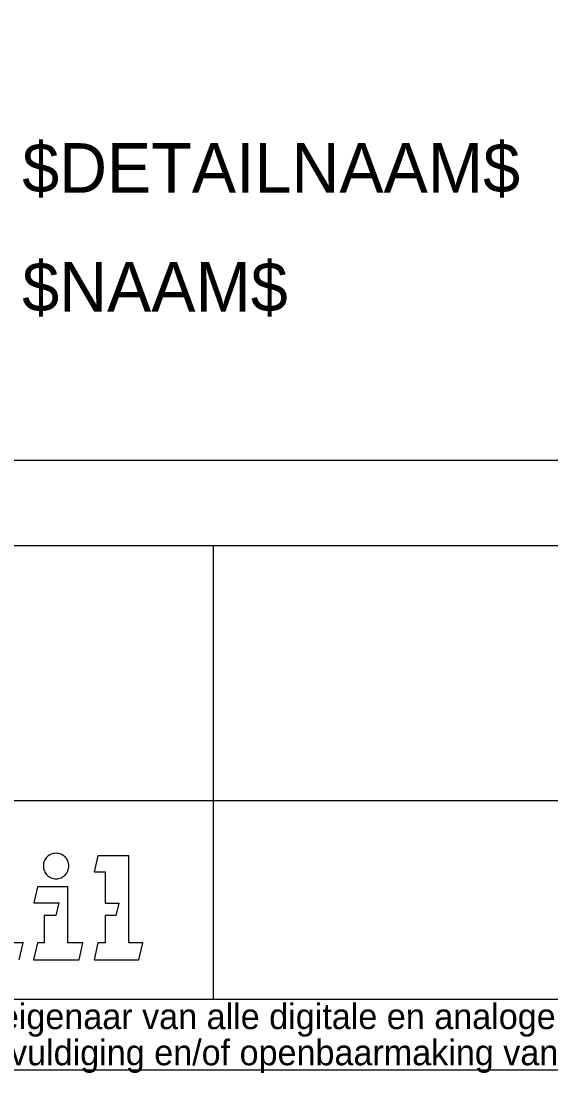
# Model space of a CAD drawing. Extents: x 0 to 1051, y 0 to 297.
# Drawn here: x 902.4 to 939.8, y -0.2 to 74 of the extents above; entities that cross this region are included whole.
import ezdxf

# ---------------------------------------------------------------- set-up
doc = ezdxf.new("R2010")
doc.units = 0
for name, color, linetype in [('KADER-LIJNEN-018', 7, 'Continuous'), ('KADER-LIJNEN-050', 7, 'Continuous'), ('TITEL-DETAIL', 7, 'Continuous'), ('TITEL-LIJNEN-050', 7, 'Continuous'), ('TITEL-PRORAIL', 7, 'Continuous'), ('TITEL-TEKSTEN-018', 7, 'Continuous')]:
    doc.layers.add(name, color=color, linetype=linetype)

msp = doc.modelspace()

# ---------------------------------------------------------------- linework, layer by layer
at = {"layer": 'KADER-LIJNEN-018'}
msp.add_line((0, 0), (1051, 0), dxfattribs=at)
at = {"layer": 'KADER-LIJNEN-050'}
msp.add_lwpolyline([(25, 5), (1046, 5), (1046, 292), (25, 292)], close=True, dxfattribs=at)
at = {"layer": 'TITEL-LIJNEN-050'}
for p, q in [((866, 37), (1046, 37)), ((916, 5), (916, 37)), ((866, 19), (1046, 19))]:
    msp.add_line(p, q, dxfattribs=at)
msp.add_lwpolyline([(866, 5), (1046, 5), (1046, 43), (866, 43)], close=True, dxfattribs=at)
at = {"layer": 'TITEL-PRORAIL'}
for p, q in [((904.147, 14.897), (904.098, 14.826)), ((904.195, 14.967), (904.147, 14.897)), ((904.255, 15.026), (904.195, 14.967)), ((904.314, 15.086), (904.255, 15.026)), ((904.384, 15.134), (904.314, 15.086)), ((904.455, 15.183), (904.384, 15.134)), ((904.536, 15.215), (904.455, 15.183)), ((904.617, 15.248), (904.536, 15.215)), ((904.703, 15.269), (904.617, 15.248)), ((904.795, 15.28), (904.703, 15.269)), ((904.886, 15.285), (904.795, 15.28)), ((904.978, 15.28), (904.886, 15.285)), ((905.065, 15.269), (904.978, 15.28)), ((905.156, 15.248), (905.065, 15.269)), ((905.237, 15.215), (905.156, 15.248)), ((905.318, 15.183), (905.237, 15.215)), ((905.389, 15.134), (905.318, 15.183)), ((905.464, 15.086), (905.389, 15.134)), ((905.524, 15.026), (905.464, 15.086)), ((905.583, 14.967), (905.524, 15.026)), ((905.637, 14.897), (905.583, 14.967)), ((905.68, 14.826), (905.637, 14.897)), ((907.845, 15.107), (907.564, 13.968)), ((910.01, 15.107), (907.845, 15.107)), ((910.01, 8.958), (910.01, 15.107)), ((904.001, 14.486), (903.996, 14.394)), ((903.996, 14.394), (904.001, 14.303)), ((904.012, 14.578), (904.001, 14.486)), ((904.001, 14.303), (904.012, 14.211)), ((904.033, 14.664), (904.012, 14.578)), ((904.012, 14.211), (904.033, 14.125)), ((904.066, 14.745), (904.033, 14.664)), ((904.033, 14.125), (904.066, 14.038)), ((904.098, 14.826), (904.066, 14.745)), ((905.718, 14.745), (905.68, 14.826)), ((905.75, 14.664), (905.718, 14.745)), ((905.718, 14.038), (905.75, 14.125)), ((905.772, 14.578), (905.75, 14.664)), ((905.75, 14.125), (905.772, 14.211)), ((905.783, 14.486), (905.772, 14.578)), ((905.772, 14.211), (905.783, 14.303)), ((905.794, 14.394), (905.783, 14.486)), ((905.783, 14.303), (905.794, 14.394)), ((904.066, 14.038), (904.098, 13.963)), ((904.098, 13.963), (904.147, 13.887)), ((904.147, 13.887), (904.195, 13.817)), ((904.195, 13.817), (904.255, 13.752)), ((904.255, 13.752), (904.314, 13.693)), ((904.314, 13.693), (904.384, 13.644)), ((904.384, 13.644), (904.455, 13.601)), ((904.455, 13.601), (904.536, 13.563)), ((904.536, 13.563), (904.617, 13.531)), ((904.617, 13.531), (904.703, 13.509)), ((904.703, 13.509), (904.795, 13.493)), ((904.795, 13.493), (904.886, 13.487)), ((904.886, 13.487), (904.978, 13.493)), ((904.978, 13.493), (905.065, 13.509)), ((905.065, 13.509), (905.156, 13.531)), ((905.156, 13.531), (905.237, 13.563)), ((905.237, 13.563), (905.318, 13.601)), ((905.318, 13.601), (905.389, 13.644)), ((905.389, 13.644), (905.464, 13.693)), ((905.464, 13.693), (905.524, 13.752)), ((905.524, 13.752), (905.583, 13.817)), ((905.583, 13.817), (905.637, 13.887)), ((905.637, 13.887), (905.68, 13.963)), ((905.68, 13.963), (905.718, 14.038)), ((907.564, 13.968), (908.342, 13.968)), ((908.342, 13.968), (908.342, 11.776)), ((903.585, 12.926), (903.321, 11.787)), ((905.707, 12.926), (903.585, 12.926)), ((905.707, 8.968), (905.707, 12.926)), ((903.321, 11.787), (905.075, 11.787)), ((905.075, 11.787), (904.865, 10.901)), ((908.342, 11.776), (909.325, 11.776)), ((909.325, 11.776), (909.114, 10.89)), ((904.865, 10.901), (904.044, 10.901)), ((904.044, 10.901), (904.044, 8.968)), ((909.114, 10.89), (908.342, 10.89)), ((908.342, 10.89), (908.342, 8.958)), ((902.565, 8.958), (901.507, 8.958)), ((902.284, 7.77), (902.565, 8.958)), ((903.585, 8.968), (903.305, 7.775)), ((904.044, 8.968), (903.585, 8.968)), ((906.787, 8.968), (905.707, 8.968)), ((906.522, 7.775), (906.787, 8.968)), ((907.829, 8.958), (907.564, 7.77)), ((908.342, 8.958), (907.829, 8.958)), ((911.009, 8.958), (910.01, 8.958)), ((910.728, 7.77), (911.009, 8.958)), ((903.305, 7.775), (906.522, 7.775)), ((907.564, 7.77), (910.728, 7.77))]:
    msp.add_line(p, q, dxfattribs=at)

# ---------------------------------------------------------------- texts
at = {"layer": 'TITEL-DETAIL'}
for s, p in [('$DETAILNAAM$', (902.5, 61.9)), ('$NAAM$', (902.5, 53.5))]:
    msp.add_text(s, height=3.5, dxfattribs=at).set_placement(p)
at = {"layer": 'TITEL-TEKSTEN-018'}
for s, p in [('ProRail is eigenaar van alle digitale en analoge verschijningsvormen van deze tekening en rechthebbende op grond van de Auteurswet 1912.', (889.952, 2.875)), ('Wijziging, vermenigvuldiging en/of openbaarmaking van deze tekening zonder voorafgaande schriftelijke toestemming van ProRail is niet toegestaan.', (880.773, 0.325))]:
    msp.add_text(s, height=1.8, dxfattribs=at).set_placement(p)

doc.saveas('drawing.dxf')
